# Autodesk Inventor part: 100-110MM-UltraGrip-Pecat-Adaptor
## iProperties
Created: 2012-05
Part Number: 100-110MM-UltraGrip-Pecat-Adaptor
Document SubType Name: Modeling
Designer: D Cole
Density: 1 g/cm^3
Author: D Cole
